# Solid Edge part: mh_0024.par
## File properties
Title: spring
Author: edge
Template: normal.par
Last saved by: edge
Revision: 38
Application: Solid Edge
Material: ABS
非切断部品: False
文書内容のタイプ: 0
Density: 0.001200 g/mm^3
Accuracy: 0.99
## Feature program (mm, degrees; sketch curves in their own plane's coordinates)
sketch for "unnamed Protrusion 1" plane through (0, 0, 0) normal (0, 0, 1) x-axis (1, 0, 0)
  line (-40, 7.5) -> (40, 7.5)
  line (40, 7.5) -> (40, -7.5)
  line (40, -7.5) -> (-40, -7.5)
  line (-40, -7.5) -> (-40, 7.5)
extrude "unnamed Protrusion 1" add finite 6 along +normal
thinwall "Thinwall_1"  Thickness = 1 mm
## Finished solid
Body 1: solid body, 11 faces, 24 edges, 16 vertices.
  Faces by surface: plane 11
  Edges by curve: line 24
Bounding box of the edges (mm): 80.000 x 15.000 x 6.000, from (-40, -7.5, 0) to (40, 7.5, 6).
Planar faces by outward normal: +x 2, +y 2, +z 1, -x 2, -y 2, -z 2
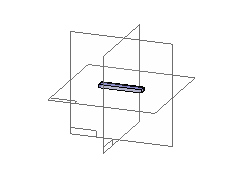
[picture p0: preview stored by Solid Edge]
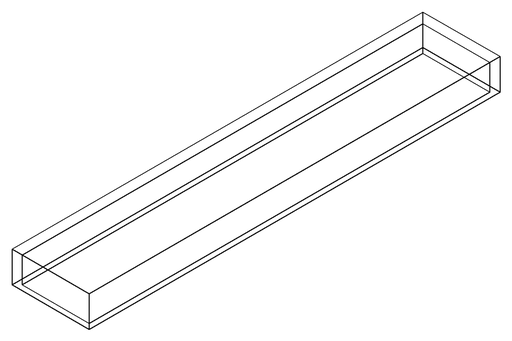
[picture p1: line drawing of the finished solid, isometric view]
